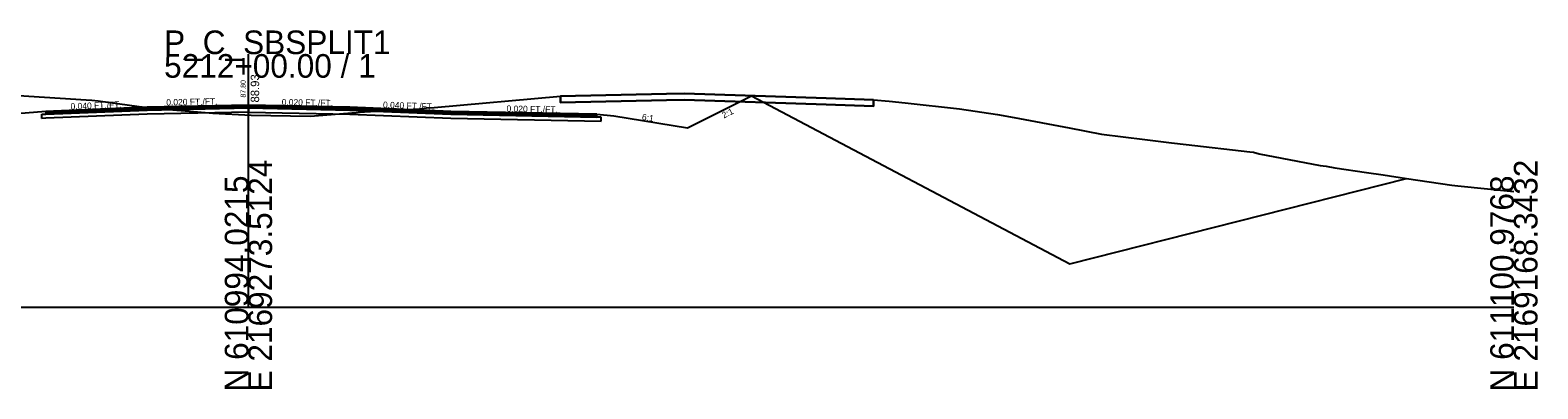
# Model space of a CAD drawing. Extents: x -26 to 1303, y -3010 to 12033.
# Drawn here: x 1124.1 to 1302.8, y 7990.3 to 8032.8 of the extents above; entities that cross this region are included whole.
import ezdxf

# ---------------------------------------------------------------- set-up
doc = ezdxf.new("R2010")
doc.units = 0
for name, color, linetype in [('RD_GPK_XS_Cell', 7, 'Continuous'), ('RD_Sketch10', 7, 'Continuous'), ('RD_XS_Base', 7, 'Continuous'), ('RD_XS_ExGround', 7, 'Continuous'), ('RD_XS_ExPaveRet', 7, 'Continuous'), ('RD_XS_Greenside', 7, 'Continuous'), ('RD_XS_Pave', 7, 'Continuous'), ('RD_XS_PaveOvlay_CP', 7, 'Continuous'), ('RD_XS_TieSlope', 7, 'Continuous'), ('RD_XS_TX_Elev_EX', 7, 'Continuous'), ('RD_XS_TX_Elev_PR', 7, 'Continuous'), ('RD_XS_TX_Slope', 7, 'Continuous')]:
    doc.layers.add(name, color=color, linetype=linetype)

msp = doc.modelspace()

# ---------------------------------------------------------------- linework, layer by layer
at = {"layer": 'RD_GPK_XS_Cell'}
for p, q in [((1150, 8000), (1150, 8030)), ((1000, 8000), (1150, 8000)), ((1150, 8000), (1300, 8000))]:
    msp.add_line(p, q, dxfattribs=at)
at = {"layer": 'RD_Sketch10'}
msp.add_lwpolyline([(1209.64, 8025.05), (1247.36, 8005.14), (1287.29, 8015.27)], dxfattribs=at)
at = {"layer": 'RD_XS_Base'}
for p, q in [((1125.5, 8022.87), (1126, 8022.89)), ((1125.5, 8022.37), (1125.5, 8022.87)), ((1125.5, 8022.87), (1125.5, 8022.87)), ((1126, 8022.89), (1138, 8023.37)), ((1126, 8022.89), (1126, 8022.89)), ((1138, 8022.87), (1126, 8022.39)), ((1136, 8023.29), (1136, 8023.29)), ((1136, 8022.79), (1136, 8022.79)), ((1138, 8023.37), (1150, 8023.61)), ((1150, 8023.11), (1138, 8022.87)), ((1150, 8023.61), (1150, 8023.77)), ((1150, 8023.77), (1150, 8023.11)), ((1150, 8023.61), (1150, 8023.11)), ((1150, 8023.61), (1150, 8023.61)), ((1162, 8023.37), (1150, 8023.61)), ((1150, 8023.61), (1150, 8023.61)), ((1150, 8023.11), (1150, 8023.11)), ((1150, 8023.11), (1150, 8023.11)), ((1150, 8023.11), (1162, 8022.87)), ((1174, 8022.89), (1162, 8023.37)), ((1162, 8023.37), (1162, 8023.37)), ((1162, 8022.87), (1162, 8022.87)), ((1162, 8022.87), (1174, 8022.39)), ((1191.3, 8022.54), (1174, 8022.89)), ((1174, 8022.89), (1174, 8022.89)), ((1191.8, 8022.53), (1191.3, 8022.54)), ((1191.3, 8022.54), (1191.3, 8022.54)), ((1191.8, 8022.03), (1191.8, 8022.53)), ((1191.8, 8022.53), (1191.8, 8022.53)), ((1126, 8022.39), (1125.5, 8022.37)), ((1125.5, 8022.37), (1125.5, 8022.37)), ((1125.5, 8022.37), (1125.5, 8022.37)), ((1126, 8022.39), (1126, 8022.39)), ((1174, 8022.39), (1174, 8022.39)), ((1174, 8022.39), (1191.8, 8022.03)), ((1191.8, 8022.03), (1191.8, 8022.03)), ((1191.8, 8022.03), (1191.8, 8022.03))]:
    msp.add_line(p, q, dxfattribs=at)
at = {"layer": 'RD_XS_ExGround'}
msp.add_lwpolyline([(1122.75, 8025.11), (1130.77, 8024.58), (1131.42, 8024.53), (1132.19, 8024.47), (1137.06, 8023.8), (1139.59, 8023.5), (1143.95, 8023.14), (1145.78, 8022.98), (1150.31, 8022.76), (1157.31, 8022.64), (1163.76, 8023.16), (1168.76, 8023.44), (1170.28, 8023.5), (1171.1, 8023.62), (1172.02, 8023.68), (1186.99, 8025.02), (1199.56, 8025.27), (1201.69, 8025.31), (1218.47, 8024.77), (1224.11, 8024.59), (1225.93, 8024.41), (1227.83, 8024.23), (1234.29, 8023.5), (1238.8, 8022.84), (1240.75, 8022.5), (1247.28, 8021.24), (1251.1, 8020.5), (1256.24, 8019.86), (1259.43, 8019.47), (1261.15, 8019.27), (1268.69, 8018.4), (1269.12, 8018.39), (1269.8, 8018.18), (1277.02, 8016.8), (1277.74, 8016.73), (1278.76, 8016.51), (1282.53, 8015.97), (1284.51, 8015.7), (1287.29, 8015.27), (1292.63, 8014.46), (1293.34, 8014.37), (1300, 8013.71)], dxfattribs=at)
at = {"layer": 'RD_XS_ExPaveRet'}
for points in [[(1224.11, 8024.59), (1224.11, 8023.84), (1224.11, 8023.84), (1224.11, 8023.84), (1224.11, 8023.84), (1218.47, 8024.02), (1218.47, 8024.02), (1201.69, 8024.56), (1201.69, 8024.56), (1199.56, 8024.52), (1199.56, 8024.52), (1186.99, 8024.27), (1186.99, 8024.27), (1186.99, 8025.02), (1199.56, 8025.27), (1199.56, 8025.27), (1201.69, 8025.31), (1201.69, 8025.31), (1218.47, 8024.77), (1218.47, 8024.77), (1224.11, 8024.59), (1224.11, 8024.59), (1224.11, 8024.59)], [(1224.11, 8024.59), (1218.47, 8024.77), (1201.69, 8025.31), (1199.56, 8025.27), (1186.99, 8025.02), (1186.99, 8024.27), (1199.56, 8024.52), (1201.69, 8024.56), (1218.47, 8024.02), (1224.11, 8023.84), (1224.11, 8023.84), (1224.11, 8024.59), (1224.11, 8024.59)]]:
    msp.add_lwpolyline(points, dxfattribs=at)
at = {"layer": 'RD_XS_Greenside'}
for p, q in [((1202.03, 8021.25), (1209.64, 8025.05)), ((1193.3, 8022.7), (1202.03, 8021.25))]:
    msp.add_line(p, q, dxfattribs=at)
at = {"layer": 'RD_XS_Pave'}
for p, q in [((1138, 8023.69), (1126, 8023.21)), ((1138, 8023.53), (1126, 8023.05)), ((1126, 8023.05), (1138, 8023.53)), ((1126, 8022.89), (1138, 8023.37)), ((1126, 8023.21), (1126, 8023.21)), ((1126, 8023.21), (1126, 8023.05)), ((1126, 8023.05), (1126, 8023.05)), ((1126, 8023.05), (1126, 8022.89)), ((1126, 8023.05), (1126, 8023.05)), ((1126, 8023.05), (1126, 8023.05)), ((1126, 8022.89), (1126, 8022.89)), ((1126, 8022.89), (1126, 8022.89)), ((1136, 8023.61), (1136, 8023.61)), ((1136, 8023.45), (1136, 8023.45)), ((1136, 8023.45), (1136, 8023.45)), ((1136, 8023.29), (1136, 8023.29)), ((1150, 8023.93), (1138, 8023.69)), ((1150, 8023.77), (1138, 8023.53)), ((1138, 8023.53), (1150, 8023.77)), ((1138, 8023.37), (1150, 8023.61)), ((1162, 8023.69), (1150, 8023.93)), ((1150, 8023.61), (1150, 8023.77)), ((1150, 8023.77), (1162, 8023.53)), ((1162, 8023.53), (1150, 8023.77)), ((1150, 8023.77), (1150, 8023.77)), ((1150, 8023.77), (1150, 8023.61)), ((1150, 8023.61), (1150, 8023.61)), ((1150, 8023.61), (1150, 8023.61)), ((1150, 8023.61), (1150, 8023.61)), ((1150, 8023.61), (1162, 8023.37)), ((1174, 8023.21), (1162, 8023.69)), ((1162, 8023.69), (1162, 8023.69)), ((1162, 8023.53), (1162, 8023.53)), ((1162, 8023.53), (1174, 8023.05)), ((1174, 8023.05), (1162, 8023.53)), ((1162, 8023.53), (1162, 8023.53)), ((1162, 8023.37), (1162, 8023.37)), ((1162, 8023.37), (1174, 8022.89)), ((1191.3, 8022.86), (1174, 8023.21)), ((1174, 8023.21), (1174, 8023.21)), ((1174, 8023.05), (1174, 8023.05)), ((1174, 8023.05), (1191.3, 8022.7)), ((1191.3, 8022.7), (1174, 8023.05)), ((1174, 8023.05), (1174, 8023.05)), ((1174, 8022.89), (1174, 8022.89)), ((1174, 8022.89), (1191.3, 8022.54)), ((1191.3, 8022.7), (1191.3, 8022.86)), ((1191.3, 8022.86), (1191.3, 8022.86)), ((1191.3, 8022.7), (1191.3, 8022.7)), ((1191.3, 8022.7), (1191.3, 8022.7)), ((1191.3, 8022.54), (1191.3, 8022.7)), ((1191.3, 8022.7), (1191.3, 8022.7)), ((1191.3, 8022.54), (1191.3, 8022.54)), ((1191.3, 8022.54), (1191.3, 8022.54))]:
    msp.add_line(p, q, dxfattribs=at)
at = {"layer": 'RD_XS_PaveOvlay_CP'}
for p, q in [((1138, 8023.69), (1126, 8023.21)), ((1126, 8023.21), (1126, 8023.21)), ((1136, 8023.61), (1136, 8023.61)), ((1150, 8023.93), (1138, 8023.69)), ((1162, 8023.69), (1150, 8023.93)), ((1174, 8023.21), (1162, 8023.69)), ((1162, 8023.69), (1162, 8023.69)), ((1191.3, 8022.86), (1174, 8023.21)), ((1174, 8023.21), (1174, 8023.21)), ((1191.3, 8022.86), (1191.3, 8022.86))]:
    msp.add_line(p, q, dxfattribs=at)
at = {"layer": 'RD_XS_TieSlope'}
for p, q in [((1126, 8023.21), (1120, 8022.73)), ((1191.3, 8022.86), (1193.3, 8022.7))]:
    msp.add_line(p, q, dxfattribs=at)

# ---------------------------------------------------------------- texts
at = {"layer": 'RD_GPK_XS_Cell'}
for s, p in [('P_C_SBSPLIT1', (1140, 8030)), ('5212+00.00 / 1', (1140, 8027.2))]:
    msp.add_text(s, height=2.8, dxfattribs=at).set_placement(p)
for s, p in [('E 2169273.5124', (1152.8, 7990)), ('E 2169168.3432', (1302.8, 7990)), ('N 610994.0215', (1150, 7990)), ('N 611100.9768', (1300, 7990))]:
    msp.add_text(s, height=2.8, rotation=90, dxfattribs=at).set_placement(p)
at = {"layer": 'RD_XS_TX_Elev_EX'}
msp.add_text('87.80', height=0.6, rotation=90, dxfattribs=at).set_placement((1149.67, 8024.85))
at = {"layer": 'RD_XS_TX_Elev_PR'}
msp.add_text('88.93', height=1, rotation=90, dxfattribs=at).set_placement((1151.27, 8024.26))
at = {"layer": 'RD_XS_TX_Slope'}
for s, rotation, p in [('0.040 FT./FT.', 2.2906, (1128.93, 8023.42)), ('0.020 FT./FT.', 1.1458, (1140.27, 8023.9)), ('0.020 FT./FT.', 358.8542, (1153.94, 8023.94)), ('0.040 FT./FT.', 357.7094, (1165.94, 8023.63)), ('0.020 FT./FT.', 358.8542, (1180.59, 8023.17)), ('6:1', 350.5377, (1196.6, 8022.21)), ('2:1', 26.5651, (1206.34, 8022.35))]:
    msp.add_text(s, height=0.75, rotation=rotation, dxfattribs=at).set_placement(p)

doc.saveas('drawing.dxf')
